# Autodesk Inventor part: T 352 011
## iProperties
Company: Mayer & Müller AG Schaltgeräte
Created: 2006-10
Part Number: T 352 011
Material: 2.0402.26
Document SubType Name: Modeling
Designer: I.Baliuc
Manufacturer: Standard
Standards Organization: Custom
Description: Lagerbuchse
Density: 8.2 g/cm^3
HalbzeugNorm: DIN 1756
Zweck: Seitenteil
Abmessung: Rd 30
Author: T.Messerschmitt
Revision Number: 352011
Keywords: 267041
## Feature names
1. Drehung1 [Revolution]
